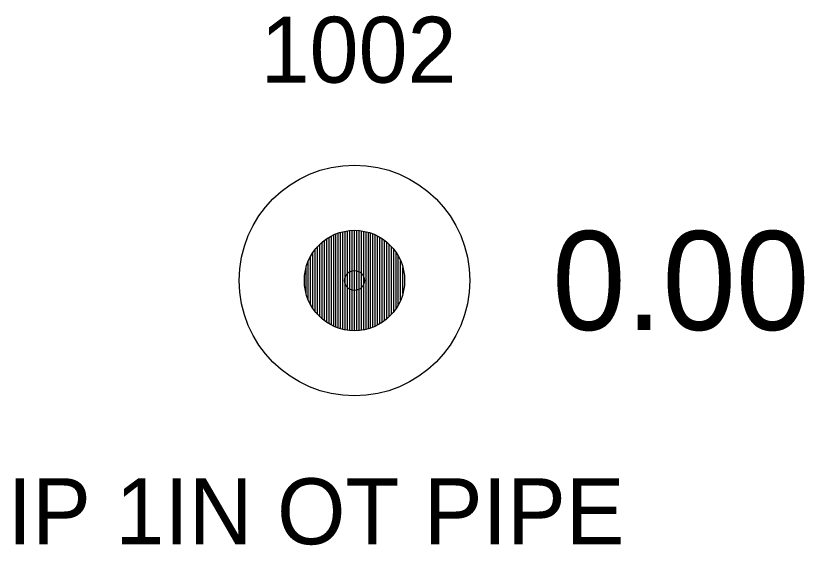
# Model space of a CAD drawing. Extents: x 1740701 to 1743138, y 748181 to 751839.
# Drawn here: x 1740827.75 to 1740839.72, y 748620.1 to 748628.13 of the extents above; entities that cross this region are included whole.
import ezdxf

# ---------------------------------------------------------------- set-up
doc = ezdxf.new("R2010")
doc.units = 0
for name, color, linetype in [('RD_EX_DV_Prop_txCode', 7, 'Continuous'), ('RD_EX_DV_PropPin', 7, 'Continuous'), ('RD_EX_TX_DV_Prop_ELEV', 7, 'Continuous'), ('RD_SMD_Locator', 7, 'Continuous')]:
    doc.layers.add(name, color=color, linetype=linetype)

msp = doc.modelspace()

# ---------------------------------------------------------------- linework, layer by layer
at = {"layer": 'RD_EX_DV_PropPin'}
for p, q in [((1740832.645, 748623.393), (1740832.645, 748624.834)), ((1740832.68, 748623.382), (1740832.68, 748624.845)), ((1740832.716, 748623.373), (1740832.716, 748624.854)), ((1740832.751, 748623.366), (1740832.751, 748624.862)), ((1740832.786, 748623.36), (1740832.786, 748624.868)), ((1740832.821, 748623.356), (1740832.821, 748624.872)), ((1740832.856, 748623.354), (1740832.856, 748624.874)), ((1740832.891, 748623.353), (1740832.891, 748624.875)), ((1740832.926, 748623.354), (1740832.926, 748624.874)), ((1740832.961, 748623.356), (1740832.961, 748624.872)), ((1740832.996, 748623.36), (1740832.996, 748624.868)), ((1740833.031, 748623.366), (1740833.031, 748624.862)), ((1740833.066, 748623.373), (1740833.066, 748624.854)), ((1740833.101, 748623.382), (1740833.101, 748624.845)), ((1740833.136, 748623.393), (1740833.136, 748624.834)), ((1740832.435, 748623.504), (1740832.435, 748624.724)), ((1740832.47, 748623.479), (1740832.47, 748624.748)), ((1740832.505, 748623.457), (1740832.505, 748624.77)), ((1740832.54, 748623.438), (1740832.54, 748624.789)), ((1740832.575, 748623.421), (1740832.575, 748624.807)), ((1740832.61, 748623.406), (1740832.61, 748624.821)), ((1740833.171, 748623.406), (1740833.171, 748624.821)), ((1740833.206, 748623.421), (1740833.206, 748624.807)), ((1740833.241, 748623.438), (1740833.241, 748624.789)), ((1740833.276, 748623.457), (1740833.276, 748624.77)), ((1740833.311, 748623.479), (1740833.311, 748624.748)), ((1740833.346, 748623.504), (1740833.346, 748624.724)), ((1740832.33, 748623.599), (1740832.33, 748624.629)), ((1740832.365, 748623.563), (1740832.365, 748624.665)), ((1740832.4, 748623.532), (1740832.4, 748624.696)), ((1740833.381, 748623.532), (1740833.381, 748624.696)), ((1740833.416, 748623.563), (1740833.416, 748624.665)), ((1740833.451, 748623.599), (1740833.451, 748624.629)), ((1740832.225, 748623.744), (1740832.225, 748624.483)), ((1740832.26, 748623.687), (1740832.26, 748624.54)), ((1740832.295, 748623.64), (1740832.295, 748624.588)), ((1740833.486, 748623.64), (1740833.486, 748624.588)), ((1740833.521, 748623.687), (1740833.521, 748624.54)), ((1740833.556, 748623.744), (1740833.556, 748624.483)), ((1740832.19, 748623.816), (1740832.19, 748624.412)), ((1740833.591, 748623.816), (1740833.591, 748624.412)), ((1740832.155, 748623.918), (1740832.155, 748624.31)), ((1740833.626, 748623.918), (1740833.626, 748624.31))]:
    msp.add_line(p, q, dxfattribs=at)
for radius in [1.75, 0.761]:
    msp.add_circle((1740832.891, 748624.114), radius, dxfattribs=at)
at = {"layer": 'RD_SMD_Locator'}
msp.add_circle((1740832.891, 748624.114), 0.15, dxfattribs=at)

# ---------------------------------------------------------------- texts
at = {"layer": 'RD_EX_DV_Prop_txCode'}
for s, p in [('1002', (1740831.465, 748627.114)), ('IP 1IN OT PIPE', (1740827.627, 748620.114))]:
    msp.add_text(s, height=1, dxfattribs=at).set_placement(p)
at = {"layer": 'RD_EX_TX_DV_Prop_ELEV'}
msp.add_text('0.00', height=1.5, dxfattribs=at).set_placement((1740835.891, 748623.364))

doc.saveas('drawing.dxf')
